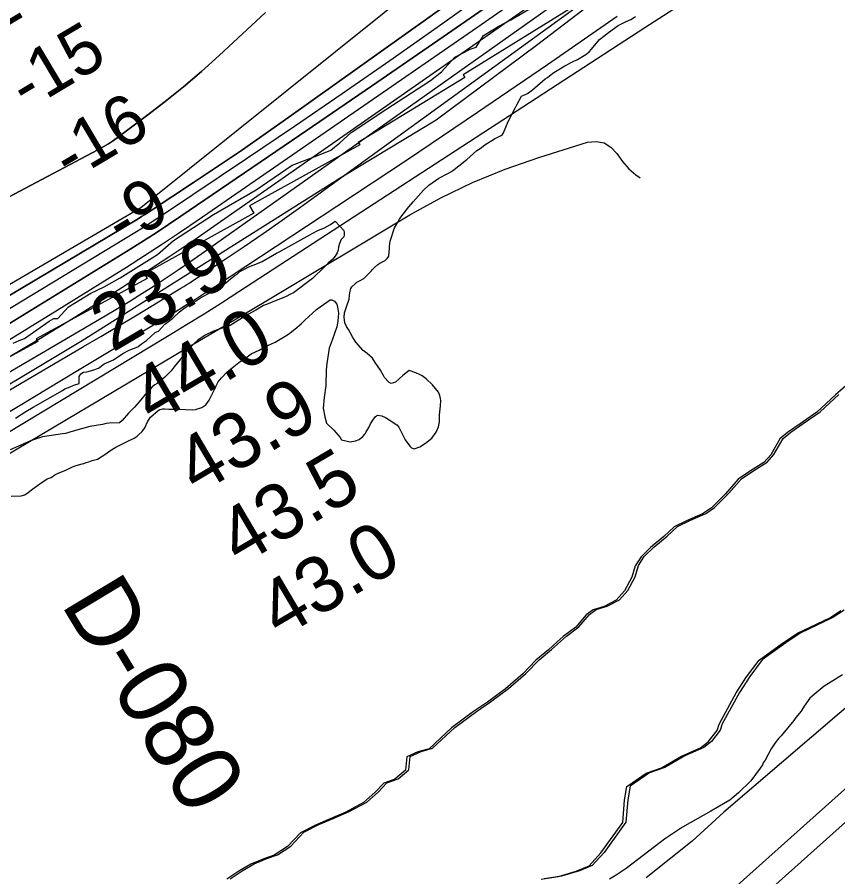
# Model space of a CAD drawing. Extents: x 3245246 to 3283090, y 806824 to 832173.
# Drawn here: x 3256343 to 3257331, y 816050 to 817086 of the extents above; entities that cross this region are included whole.
import ezdxf

# ---------------------------------------------------------------- set-up
doc = ezdxf.new("R2010")
doc.units = 0
for name, color, linetype in [('V-LEVE-TOET', 7, 'Continuous'), ('V-RIVR-EDGE', 7, 'Continuous'), ('V-RIVR-RANG', 7, 'Continuous'), ('V-RIVR-RANG-IDEN', 7, 'Continuous'), ('V-RRAP-FSHR', 7, 'Continuous'), ('V-RRAP-RVMT', 7, 'Continuous'), ('V-SITE-VEGE', 7, 'Continuous'), ('V-SURV-LINE', 7, 'Continuous'), ('V-TOPO-DPTH', 7, 'Continuous'), ('V-TOPO-MAJR', 7, 'Continuous'), ('V-TOPO-MINR', 7, 'Continuous'), ('V-TOPO-SHOR', 7, 'Continuous'), ('V-TOPO-WATR', 7, 'Continuous')]:
    doc.layers.add(name, color=color, linetype=linetype)

msp = doc.modelspace()

# ---------------------------------------------------------------- linework, layer by layer
at = {"layer": 'V-LEVE-TOET'}
msp.add_lwpolyline([(3258211.2, 817024.1), (3258056.3, 816883.7), (3257899.2, 816745.8), (3257856.8, 816704.1), (3257736.1, 816602.1), (3257675.3, 816549.6), (3257651.4, 816529.3), (3257590.5, 816473.8), (3257561.6, 816445.6), (3257524.4, 816410.7), (3257505.4, 816395.8), (3257488.1, 816384.5), (3257466.2, 816366.5), (3257441.6, 816345.9), (3257417, 816319.7), (3257369.1, 816277.5), (3257194, 816127.7), (3257155.7, 816092.8), (3257100.6, 816048.3)], dxfattribs=at)
at = {"layer": 'V-RIVR-EDGE'}
for points in [[(3256870.1, 817037.4), (3256888.4, 817047.3), (3256895.8, 817049.5), (3256904.5, 817063.8), (3256922.8, 817075), (3256937.2, 817082.4), (3256968.1, 817100.6)], [(3256337.7, 816692.7), (3256345.1, 816696.1), (3256351.6, 816698.3), (3256381.2, 816719.5), (3256386.8, 816722.5), (3256391.6, 816722.5), (3256404.3, 816736.4), (3256431.3, 816752.9), (3256447.4, 816760.6), (3256466.9, 816771.5), (3256511.8, 816799.6), (3256531, 816816.5), (3256579.3, 816847.7), (3256630.7, 816877.5), (3256673.8, 816907.4), (3256703.8, 816918.7), (3256720.7, 816925.6), (3256731.2, 816934.2), (3256745.1, 816946.8), (3256786.9, 816974.5), (3256840.5, 817009.2), (3256854, 817020), (3256870.1, 817037.4)]]:
    msp.add_lwpolyline(points, dxfattribs=at)
at = {"layer": 'V-RRAP-FSHR'}
msp.add_lwpolyline([(3256099.8, 816503.6), (3256421.1, 816696), (3256733.8, 816893.2), (3256847.6, 816962), (3256970, 817053.3), (3257093.6, 817148), (3257266.7, 817284.2), (3257388.9, 817386.6), (3257469, 817470.2), (3257525.1, 817541.5), (3257588.2, 817612.1), (3257698.7, 817689), (3257767, 817744.6), (3257833, 817785.6), (3257894.4, 817818.3), (3257965.2, 817866.9), (3258035, 817924.4), (3258124.2, 817980.8), (3258147.2, 817993.5)], dxfattribs=at)
at = {"layer": 'V-RRAP-RVMT'}
for p, q in [((3257007.2, 817094.9), (3256879.9, 817016.4)), ((3257007.2, 817094.9), (3256879.9, 817016.4)), ((3256882, 817012.8), (3256753.6, 816934.8)), ((3256882, 817012.8), (3256753.6, 816934.8)), ((3256879.9, 817016.4), (3256882, 817012.8)), ((3256879.9, 817016.4), (3256882, 817012.8)), ((3256755.3, 816931.7), (3256622.7, 816858.5)), ((3256755.3, 816931.7), (3256622.7, 816858.5)), ((3256753.6, 816934.8), (3256755.3, 816931.7)), ((3256753.6, 816934.8), (3256755.3, 816931.7)), ((3256622.7, 816858.5), (3256627.6, 816849.6)), ((3256622.7, 816858.5), (3256627.6, 816849.6)), ((3256627.6, 816849.6), (3256495.9, 816776.3)), ((3256627.6, 816849.6), (3256495.9, 816776.3)), ((3256499.1, 816770.7), (3256365.7, 816697.9)), ((3256499.1, 816770.7), (3256365.7, 816697.9)), ((3256495.9, 816776.3), (3256499.1, 816770.7)), ((3256495.9, 816776.3), (3256499.1, 816770.7)), ((3256365.7, 816697.9), (3256367.4, 816694.8)), ((3256365.7, 816697.9), (3256367.4, 816694.8)), ((3256367.4, 816694.8), (3256235.2, 816622.6)), ((3256367.4, 816694.8), (3256235.2, 816622.6))]:
    msp.add_line(p, q, dxfattribs=at)
at = {"layer": 'V-SITE-VEGE'}
for points in [[(3256807.3, 816654), (3256798.6, 816645.7), (3256795.9, 816644.9), (3256793.1, 816644.2), (3256790.8, 816645.4), (3256785, 816651.5), (3256783.9, 816653.8), (3256780.2, 816660.3), (3256774.1, 816669.7), (3256770.8, 816674.7), (3256764.4, 816680.2), (3256759.4, 816684), (3256750.5, 816694.2), (3256747.1, 816699.5), (3256741.7, 816709.1), (3256739.2, 816712.9), (3256737.3, 816717.4), (3256736.4, 816724), (3256736.9, 816729.3), (3256740.3, 816739.2), (3256741.9, 816743.3), (3256742.5, 816745.8), (3256743.1, 816750.5), (3256743.6, 816753.4), (3256743.8, 816755.6), (3256744.6, 816758.5), (3256746, 816760.6), (3256749.7, 816764.5), (3256751.9, 816766.2), (3256756, 816768.3), (3256760.3, 816770.8), (3256769.2, 816779.5), (3256770.4, 816781.2), (3256773, 816784.1), (3256777.3, 816787.6), (3256779.5, 816789.1), (3256785.9, 816792.6), (3256788.5, 816794.7), (3256790.3, 816797.6), (3256790.7, 816802.9), (3256791.2, 816806.4), (3256791.2, 816809.3), (3256791.6, 816812.6), (3256792.2, 816815.9), (3256797.3, 816831.7), (3256801.1, 816838.7), (3256803.1, 816842.2), (3256805, 816844.7), (3256814.5, 816857.1), (3256819.7, 816863.3), (3256832.3, 816877.2), (3256838.6, 816883.2), (3256850.6, 816891.8), (3256861.4, 816897.4), (3256865.7, 816899.7), (3256869.3, 816902), (3256874.8, 816906.4), (3256884.4, 816914.3), (3256896.5, 816924.9), (3256900.6, 816927.6), (3256906.1, 816931.8), (3256917.7, 816939.1), (3256921.8, 816941.2), (3256925.7, 816942.9), (3256927.5, 816944.1), (3256928.7, 816946.4), (3256934.3, 816959.8), (3256937.9, 816966.8), (3256939.9, 816970.9), (3256943.1, 816976.7), (3256945.1, 816980.8), (3256950.4, 816990.3), (3256957.4, 816993.7), (3256960.3, 816995.8), (3256963.7, 816998.7), (3256966.4, 817000.6), (3256978.8, 817011.2), (3256981.4, 817012.8), (3256984.1, 817015.1), (3256989.3, 817018.9), (3257002.6, 817027), (3257011.8, 817032), (3257017.7, 817034.8), (3257027.9, 817040.8), (3257031.7, 817043.9), (3257034.6, 817047.1), (3257044.3, 817058.6), (3257049.6, 817063), (3257055.2, 817067.4), (3257066.8, 817075.7), (3257076.2, 817080.5), (3257082.1, 817082.9), (3257085, 817084.7), (3257087.4, 817086.6)], [(3256410.8, 816642.2), (3256417.3, 816644.4), (3256417.5, 816648.5), (3256417.5, 816652.8), (3256419.5, 816655.9), (3256422.7, 816657.7), (3256426.4, 816658.4), (3256433.8, 816660.3), (3256440.5, 816662.5), (3256447.6, 816667.9), (3256458.6, 816672.7), (3256469.8, 816680.2), (3256477.7, 816684.2), (3256488.2, 816688.5), (3256492.6, 816692.1), (3256498.5, 816695.9), (3256508.9, 816705.6), (3256512.8, 816707.4), (3256520.5, 816715.6), (3256525, 816718.8), (3256530.3, 816722.9), (3256538.2, 816730.4), (3256543.3, 816734.6), (3256547.3, 816737.3), (3256554.9, 816741.7), (3256564.8, 816748.1), (3256568.1, 816749.8), (3256572.2, 816752.3), (3256576.9, 816754.8), (3256581.6, 816756.9), (3256585, 816758.8), (3256589.1, 816761.5), (3256599.5, 816770.3), (3256604.9, 816774.4), (3256607.6, 816776.1), (3256611, 816779), (3256616.5, 816782.1), (3256621.9, 816784.7), (3256626.8, 816786.8), (3256632.3, 816788.7), (3256637.8, 816791.2), (3256654.9, 816801.2), (3256659.2, 816803.3), (3256677.3, 816813.2), (3256687.9, 816819.4), (3256695.2, 816823.2), (3256697.9, 816824.9), (3256705.6, 816828.9), (3256712.8, 816831.8), (3256720.1, 816836), (3256725.9, 816839.9), (3256736, 816828.6), (3256736.5, 816826.3), (3256736.5, 816823.4), (3256736.1, 816821), (3256733.1, 816817.7), (3256730.9, 816813.1), (3256729.9, 816808.8), (3256729.3, 816804.7), (3256728.3, 816801.8), (3256725.9, 816797.5), (3256723.1, 816794), (3256720.7, 816792.1), (3256717.2, 816789.2), (3256712.9, 816784.8), (3256698.3, 816770.7), (3256675.4, 816753.4), (3256672.1, 816751.8), (3256666.6, 816749.2), (3256648, 816741.4), (3256642.9, 816739.5), (3256639.4, 816738.1)], [(3256475.8, 816574.8), (3256483.5, 816578.4), (3256487, 816580.7), (3256489.2, 816582.6), (3256493.3, 816586.5), (3256496.5, 816590.9), (3256499.9, 816598.7), (3256503.2, 816603.5), (3256512.5, 816611.8), (3256514.7, 816613), (3256517.6, 816613.5), (3256520.1, 816613.5), (3256525.4, 816613.1), (3256536.5, 816613.3), (3256554.3, 816612.4), (3256557.6, 816612.7), (3256565.2, 816615.2), (3256569.8, 816618.6), (3256573.9, 816624.3), (3256581.1, 816638.6), (3256581.9, 816640.6), (3256583.3, 816643.1), (3256584.7, 816646.2), (3256588.7, 816651.2), (3256595.8, 816658.2), (3256601.5, 816663.2), (3256609.7, 816669.7), (3256621.3, 816677.6), (3256624.7, 816680.1), (3256634.1, 816684.5), (3256641, 816688.5), (3256653.3, 816694.1), (3256669.4, 816703.5), (3256677.1, 816709.6), (3256684.6, 816716), (3256689.1, 816720.4), (3256703.1, 816733.2), (3256707.5, 816736.6), (3256719.7, 816744.9), (3256721.8, 816744.9), (3256724.9, 816743.3), (3256726.3, 816741.7), (3256727.6, 816739.7), (3256728.5, 816736), (3256729.6, 816729), (3256728.9, 816719.4), (3256727.7, 816712.6), (3256722.3, 816696.5), (3256718.6, 816686.9), (3256715.5, 816668.2), (3256715, 816660.6), (3256714.3, 816641.9), (3256712.5, 816627.3), (3256711.2, 816614.4), (3256713.1, 816604), (3256715.3, 816596.4), (3256724.2, 816588.1), (3256731.9, 816579), (3256733.5, 816576.5), (3256743.8, 816574), (3256750.4, 816575.1), (3256754.6, 816576.7), (3256757.1, 816578.6), (3256759.1, 816580.5), (3256761.8, 816583.4), (3256762.6, 816585.2), (3256765.2, 816589), (3256766.4, 816591), (3256768.4, 816595.4), (3256771, 816600.1), (3256774.2, 816604.6), (3256776.9, 816606.1), (3256782, 816605.4), (3256786.5, 816603.4), (3256795.4, 816597.5), (3256797.9, 816595.7), (3256800, 816594.5), (3256802.5, 816591.4), (3256810.2, 816576.3), (3256815.6, 816568.8), (3256817.9, 816566.8), (3256821, 816565.6), (3256827.8, 816567.7), (3256834.7, 816572.3), (3256842, 816578.5), (3256847.4, 816585.4), (3256850.4, 816592), (3256851.4, 816598.1), (3256851.3, 816606.3), (3256852.6, 816617.2), (3256853, 816623.6), (3256852.5, 816626.2), (3256851.7, 816629.9), (3256850.4, 816633.6), (3256842.9, 816642.5), (3256835.4, 816649.8), (3256830.7, 816653.3), (3256828.2, 816654.7), (3256823.1, 816656.9), (3256814.8, 816659.7), (3256807.3, 816654)], [(3256639.4, 816738.1), (3256630.3, 816732.6), (3256620.7, 816727.4), (3256599.1, 816714), (3256584.8, 816709.4), (3256579.3, 816707.2), (3256569.3, 816702.4), (3256560.1, 816696.4), (3256556.3, 816692.8), (3256551.2, 816687.7), (3256545.1, 816680.8), (3256539.3, 816673.4), (3256531.8, 816664.3), (3256528, 816659.5), (3256520.5, 816651.8), (3256511.1, 816644.3), (3256508.5, 816642.5), (3256505.4, 816640), (3256502.8, 816637.5), (3256498.7, 816633.3), (3256489.8, 816622.2), (3256483.9, 816615.5), (3256476.6, 816608.3), (3256469, 816599.8), (3256465.9, 816596.9), (3256453.6, 816596.2), (3256450, 816595.9), (3256445.3, 816594.6), (3256430, 816592.2), (3256410.1, 816586.6), (3256400.8, 816583.9), (3256397.4, 816583.6), (3256381.2, 816581), (3256373.2, 816580), (3256358.6, 816575.3), (3256350.6, 816571.3), (3256334, 816564.4)], [(3257346.9, 816646.7), (3257328.7, 816630.7), (3257306, 816609.8), (3257285.8, 816595.5), (3257270.8, 816585.2), (3257261.5, 816577.6), (3257250.5, 816558.3), (3257242.2, 816549), (3257226.3, 816539), (3257211.3, 816529), (3257196, 816511.4), (3257179.1, 816494.5), (3257168.4, 816487.2), (3257149.1, 816478.5), (3257134.2, 816471.6), (3257121.9, 816459.9), (3257105.6, 816446.7), (3257094.3, 816435.4), (3257087.3, 816424.4), (3257083.3, 816410.8), (3257074.4, 816394.5), (3257064.4, 816383.2), (3257049.8, 816375.6), (3257036.5, 816371.6), (3257028.1, 816365.3), (3257015.5, 816350.6), (3257000.6, 816339.3), (3256993.2, 816332.7), (3256982.6, 816323.4), (3256967.6, 816310.8), (3256951.7, 816294.2), (3256930.8, 816276.2), (3256909.1, 816260.3), (3256892.2, 816248.7), (3256865.9, 816229.4), (3256839, 816204.1), (3256825.4, 816200.2)], [(3256340.5, 816602.5), (3256353.1, 816610.5), (3256362.1, 816615.8), (3256397.3, 816635.7), (3256400.2, 816637.6), (3256406.3, 816640.1), (3256410.8, 816642.2)], [(3256335.4, 816508.4), (3256347.3, 816508.8), (3256351.7, 816510.1), (3256355.7, 816512.7), (3256361.6, 816517.4), (3256369.9, 816523.4), (3256378.6, 816529.3), (3256381.2, 816530.3), (3256383.6, 816531), (3256388.2, 816534.3), (3256392.2, 816536), (3256397.2, 816538.3), (3256401.9, 816540), (3256409.2, 816543.6), (3256413.8, 816545.3), (3256420.8, 816547.3), (3256423.1, 816547.9), (3256425.8, 816548.9), (3256428.8, 816549.6), (3256432.8, 816551.6), (3256439.3, 816553.1), (3256449.5, 816559.4), (3256454.4, 816562.9), (3256461.5, 816567.3), (3256475.8, 816574.8)], [(3256973.8, 816046.8), (3256994.7, 816050.1), (3257016, 816056.4), (3257031.6, 816062.8), (3257045.9, 816078.7), (3257072.2, 816115.3), (3257074.5, 816142.2), (3257077.2, 816158.5), (3257100.4, 816174.4), (3257119, 816181), (3257143, 816195), (3257165.9, 816205), (3257175.2, 816212.3), (3257185.9, 816225.9), (3257188.2, 816233.5), (3257208.8, 816271.4), (3257221.4, 816290.7), (3257236.4, 816310.6), (3257264.6, 816331.2), (3257282.9, 816343.5), (3257321.5, 816361.8), (3257335.1, 816370.7)], [(3257337.1, 816293), (3257325.5, 816285.7), (3257314.9, 816279.4), (3257300.3, 816267.5), (3257297.6, 816264.8), (3257290.9, 816255.5), (3257287, 816249.5), (3257280.6, 816241.6), (3257278.3, 816238.2), (3257263, 816219.6), (3257260.4, 816216.6), (3257256, 816211.3), (3257253.4, 816207.7), (3257251.1, 816204), (3257243.7, 816190.4), (3257241.4, 816187.1), (3257240.4, 816184.7), (3257237.8, 816180.7), (3257226.4, 816165.5), (3257211.8, 816150.8), (3257201.2, 816141.9), (3257178.2, 816128.6), (3257144.3, 816109.3), (3257122.4, 816095)], [(3256825.4, 816200.2), (3256812.1, 816194.2), (3256810.4, 816178.2), (3256797.8, 816167.3), (3256784.2, 816162.6), (3256773.5, 816151.3), (3256759.9, 816139.4), (3256738.6, 816127.7), (3256719.7, 816119.4), (3256702.1, 816112.1), (3256684.1, 816102.8), (3256668.5, 816086.2), (3256652.2, 816075.6), (3256639.6, 816071.3), (3256624.3, 816065), (3256609.7, 816056.3), (3256595.4, 816047)], [(3257122.4, 816095), (3257117.4, 816091.1), (3257076.2, 816059.5), (3257064.2, 816051.5), (3257056.3, 816046.9)]]:
    msp.add_lwpolyline(points, dxfattribs=at)
at = {"layer": 'V-SURV-LINE'}
for points in [[(3257046.5, 815892.9), (3259111.3, 817740.4)], [(3259131.3, 817718.1), (3257066.5, 815870.5)]]:
    msp.add_lwpolyline(points, dxfattribs=at)
at = {"layer": 'V-TOPO-DPTH'}
for points in [[(3257313.2, 817423.9), (3256670.1, 816965.1), (3256641.6, 816945.1), (3256613, 816925.2), (3256584.1, 816905.6), (3256555.1, 816886.3), (3256505.2, 816853.4), (3256501, 816850.7), (3256496.8, 816848), (3256492.6, 816845.4), (3256488.3, 816842.8), (3256031.6, 816570.7)], [(3256031.6, 816570.7), (3256488.3, 816842.8), (3256492.6, 816845.4), (3256496.8, 816848), (3256501, 816850.7), (3256505.2, 816853.4), (3256555.1, 816886.3), (3256584.1, 816905.6), (3256613, 816925.2), (3256641.6, 816945.1), (3256670.1, 816965.1), (3257313.2, 817423.9)], [(3256941.6, 817122), (3256855.8, 817062), (3256769.7, 817002.5), (3256683.3, 816943.3), (3256539.9, 816845.7), (3256525, 816835.7), (3256509.9, 816825.8), (3256494.8, 816816.2), (3256479.5, 816806.6), (3256333.3, 816716.6)], [(3256941.6, 817122), (3256855.8, 817062), (3256769.7, 817002.5), (3256683.3, 816943.3), (3256539.9, 816845.7), (3256525, 816835.7), (3256509.9, 816825.8), (3256494.8, 816816.2), (3256479.5, 816806.6), (3256333.3, 816716.6)], [(3256330.9, 816675.3), (3256370.6, 816698.9), (3256409.9, 816723.1), (3256449.1, 816747.5), (3256468.7, 816760), (3256497.8, 816778.7), (3256526.6, 816797.7), (3256555.3, 816817), (3256583.7, 816836.6), (3256973.8, 817109.5)], [(3256149.9, 816772.3), (3256439.9, 816925.8), (3256446.3, 816929.4), (3256452.5, 816933.1), (3256458.6, 816937.1), (3256464.6, 816941.4), (3256498.5, 816966.6), (3256521.1, 816984), (3256543.2, 817001.8), (3256564.8, 817020.4), (3256586, 817039.4), (3256641.7, 817091.2)], [(3256641.7, 817091.2), (3256586, 817039.4), (3256564.8, 817020.4), (3256543.2, 817001.8), (3256521.1, 816984), (3256498.5, 816966.6), (3256464.6, 816941.4), (3256458.6, 816937.1), (3256452.5, 816933.1), (3256446.3, 816929.4), (3256439.9, 816925.8), (3256149.9, 816772.3)]]:
    msp.add_lwpolyline(points, dxfattribs=at)
at = {"layer": 'V-TOPO-MAJR'}
msp.add_lwpolyline([(3256273.1, 816574.3), (3256344.3, 816616.9), (3256415.5, 816659.7), (3256532.9, 816730.7), (3256545.2, 816738.3), (3256557.4, 816745.9), (3256569.5, 816753.7), (3256581.6, 816761.5), (3256727.9, 816857.8), (3256812.8, 816914.2), (3256897.4, 816971.1), (3256981.5, 817028.7), (3257065.3, 817086.8)], dxfattribs=at)
at = {"layer": 'V-TOPO-MINR'}
for points in [[(3256031.6, 816570.7), (3256488.3, 816842.8), (3256492.6, 816845.4), (3256496.8, 816848), (3256501, 816850.7), (3256505.2, 816853.4), (3256555.1, 816886.3), (3256584.1, 816905.6), (3256613, 816925.2), (3256641.6, 816945.1), (3256670.1, 816965.1), (3257313.2, 817423.9)], [(3256188.2, 816646.7), (3256484.2, 816826.1), (3256493.6, 816831.9), (3256502.9, 816837.7), (3256512.1, 816843.7), (3256521.3, 816849.8), (3256619, 816915.2), (3256676.8, 816954.3), (3256734.3, 816993.7), (3256791.6, 817033.6), (3256848.6, 817073.8), (3257308.6, 817401.6)], [(3256114, 816529.8), (3256448.5, 816725.8), (3256463.4, 816734.7), (3256478.2, 816743.6), (3256492.9, 816752.8), (3256507.6, 816762), (3256522.1, 816771.5), (3256536.5, 816781.1), (3256550.8, 816790.9), (3256565, 816800.8), (3257152.9, 817217.3)], [(3255874.7, 816495.5), (3256491.8, 816856.5), (3256902, 817185.6)], [(3255826.2, 816338.2), (3256422.6, 816688.6), (3256443.4, 816700.9), (3256464.2, 816713.3), (3256485, 816725.7), (3256505.7, 816738.2), (3256540, 816759.1), (3256543.5, 816761.3), (3256547, 816763.4), (3256550.5, 816765.7), (3256553.9, 816767.9), (3256593.2, 816794), (3256616.2, 816809.5), (3256639, 816825.1), (3256661.7, 816841), (3256684.2, 816857.2), (3257067.2, 817135.3)], [(3256327.1, 816693.1), (3256391, 816732.4), (3256474.3, 816784.5), (3256496.2, 816798.4), (3256517.9, 816812.4), (3256539.4, 816826.8), (3256560.8, 816841.3), (3256794.1, 817002.4), (3256886, 817066), (3256977.7, 817129.9)], [(3256219.4, 816517.8), (3256525.7, 816702.5), (3256546.8, 816715.3), (3256567.8, 816728.3), (3256588.7, 816741.5), (3256609.5, 816754.9), (3257098.8, 817073.2), (3257150.8, 817107.1)], [(3256330.9, 816675.3), (3256370.6, 816698.9), (3256409.9, 816723.1), (3256449.1, 816747.5), (3256468.7, 816760), (3256497.8, 816778.7), (3256526.6, 816797.7), (3256555.3, 816817), (3256583.7, 816836.6), (3256973.8, 817109.5)], [(3256149.9, 816772.3), (3256439.9, 816925.8), (3256446.3, 816929.4), (3256452.5, 816933.1), (3256458.6, 816937.1), (3256464.6, 816941.4), (3256498.5, 816966.6), (3256521.1, 816984), (3256543.2, 817001.8), (3256564.8, 817020.4), (3256586, 817039.4), (3256641.7, 817091.2)], [(3255948.9, 816331.8), (3256517, 816669.1), (3256548.8, 816688), (3256580.6, 816706.9), (3256612.3, 816725.8), (3256644.1, 816744.8), (3256815.8, 816847.4), (3256853.2, 816867.9), (3256891.3, 816886.6), (3256930.7, 816902.5), (3256971, 816916.6), (3257029.9, 816934.9), (3257040.3, 816935.8), (3257049.7, 816934.3), (3257057.8, 816929.1), (3257065, 816921.5), (3257071.8, 816911.9), (3257079.4, 816903.1), (3257088.1, 816895.5), (3257093.2, 816891.9)]]:
    msp.add_lwpolyline(points, dxfattribs=at)
at = {"layer": 'V-TOPO-SHOR'}
for points in [[(3256763.8, 816139.8), (3256777.4, 816151.7), (3256788, 816163), (3256801.7, 816167.7), (3256814.3, 816178.7), (3256816, 816194.6), (3256829.2, 816200.6), (3256842.9, 816204.6), (3256869.8, 816229.8), (3256896.1, 816249.1), (3256913, 816260.7), (3256934.6, 816276.7), (3256955.6, 816294.6), (3256971.5, 816311.2), (3256986.5, 816323.8), (3256997.1, 816333.1), (3257004.4, 816339.8), (3257019.4, 816351.1), (3257032, 816365.7), (3257040.3, 816372), (3257053.6, 816376), (3257068.2, 816383.6), (3257078.2, 816394.9), (3257087.2, 816411.2), (3257091.2, 816424.8), (3257098.2, 816435.8), (3257109.5, 816447.1), (3257125.8, 816460.4), (3257138.1, 816472), (3257153, 816479), (3257172.3, 816487.6), (3257182.9, 816494.9), (3257199.9, 816511.9), (3257215.2, 816529.5), (3257230.1, 816539.4), (3257246.1, 816549.4), (3257254.4, 816558.7), (3257265.4, 816578), (3257274.7, 816585.6), (3257289.6, 816595.9), (3257309.9, 816610.2), (3257332.5, 816631.1)], [(3257339, 816371.2), (3257325.4, 816362.2), (3257286.8, 816343.9), (3257268.5, 816331.6), (3257240.3, 816311), (3257225.3, 816291.1), (3257212.7, 816271.8), (3257192.1, 816234), (3257189.7, 816226.3), (3257179.1, 816212.7), (3257169.8, 816205.4), (3257146.8, 816195.4), (3257122.9, 816181.5), (3257104.3, 816174.8), (3257081, 816158.9), (3257078.4, 816142.6), (3257076, 816115.7), (3257049.8, 816079.1), (3257035.5, 816063.2), (3257019.9, 816056.9), (3256998.6, 816050.6), (3256977.6, 816047.3)], [(3256599.2, 816047.4), (3256613.5, 816056.7), (3256628.1, 816065.4), (3256643.4, 816071.7), (3256656.1, 816076), (3256672.4, 816086.6), (3256688, 816103.3), (3256705.9, 816112.6), (3256723.5, 816119.9), (3256742.5, 816128.2), (3256763.8, 816139.8)]]:
    msp.add_lwpolyline(points, dxfattribs=at)
at = {"layer": 'V-TOPO-WATR'}
msp.add_lwpolyline([(3256333.3, 816716.6), (3256479.5, 816806.6), (3256494.8, 816816.2), (3256509.9, 816825.8), (3256525, 816835.7), (3256539.9, 816845.7), (3256683.3, 816943.3), (3256769.7, 817002.5), (3256855.8, 817062), (3256941.6, 817122)], dxfattribs=at)

# ---------------------------------------------------------------- texts
at = {"layer": 'V-RIVR-RANG'}
for s, height, rotation, p in [('-26', 60, 30.8353, (3256291.4, 817051.2)), ('-15', 60, 30.8353, (3256354.2, 816972.3)), ('-16', 60, 30.8353, (3256406.4, 816887)), ('-9', 60, 30.8353, (3256469.4, 816808.2)), ('23.9', 67, 30.5483, (3256457.4, 816681.1)), ('44.0', 67, 30.5483, (3256506.2, 816593.8)), ('43.9', 67, 30.5483, (3256559.5, 816509.2)), ('43.5', 67, 30.5483, (3256610.8, 816423.3)), ('43.0', 67, 30.5483, (3256659.3, 816335.8))]:
    msp.add_text(s, height=height, rotation=rotation, dxfattribs=at).set_placement(p)
at = {"layer": 'V-RIVR-RANG-IDEN'}
msp.add_text('D-080', height=83, rotation=301.0873, dxfattribs=at).set_placement((3256394.5, 816378.7))

doc.saveas('drawing.dxf')
